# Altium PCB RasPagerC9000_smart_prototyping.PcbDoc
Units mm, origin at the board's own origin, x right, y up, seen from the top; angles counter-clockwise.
Board outline 40.39 x 44.45 mm, 2 copper layers (Top Layer, Bottom Layer); 31 components, 33 nets, 123 pads, 25 vias.
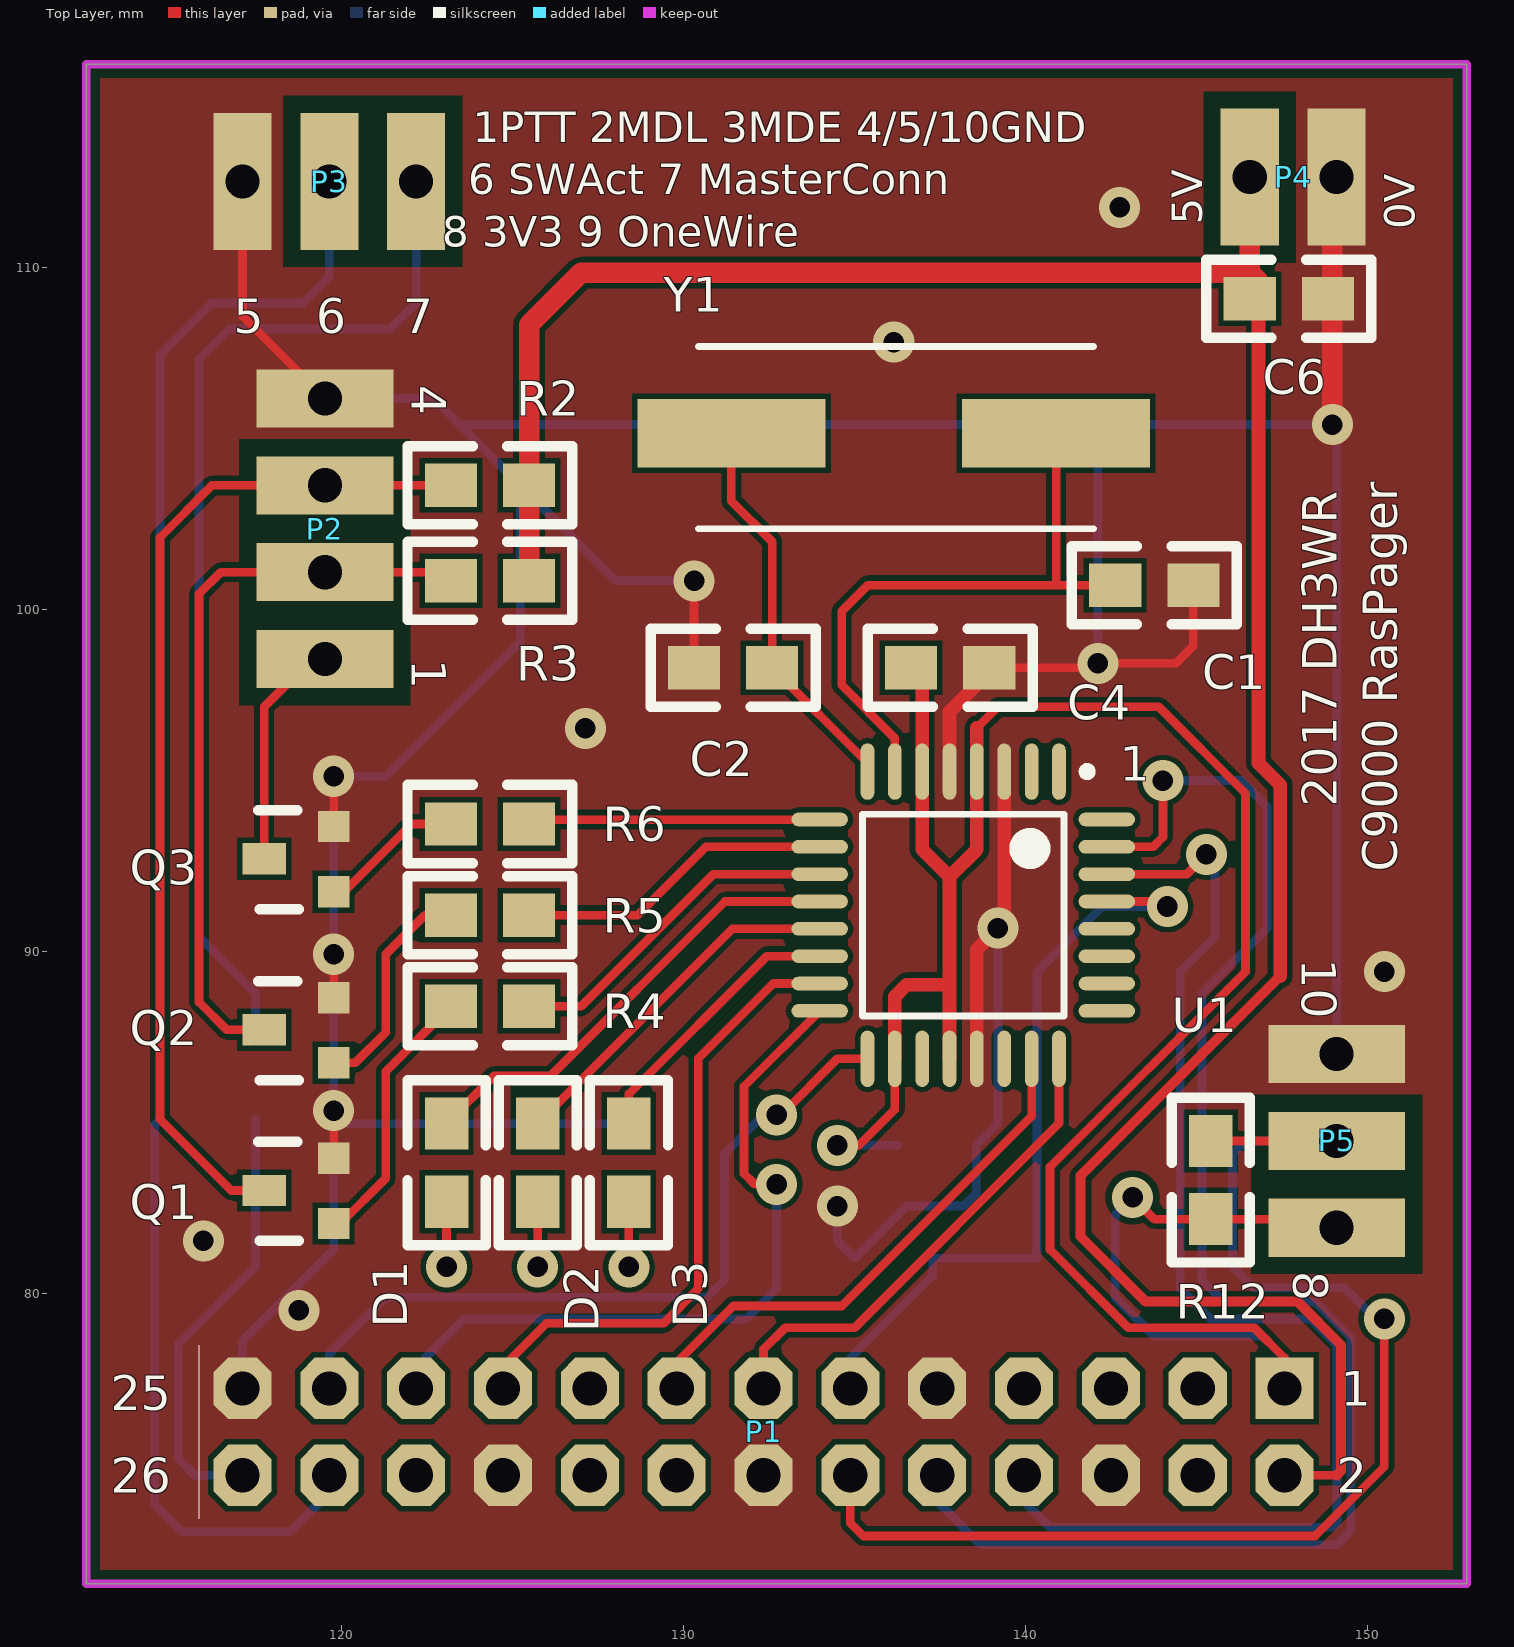
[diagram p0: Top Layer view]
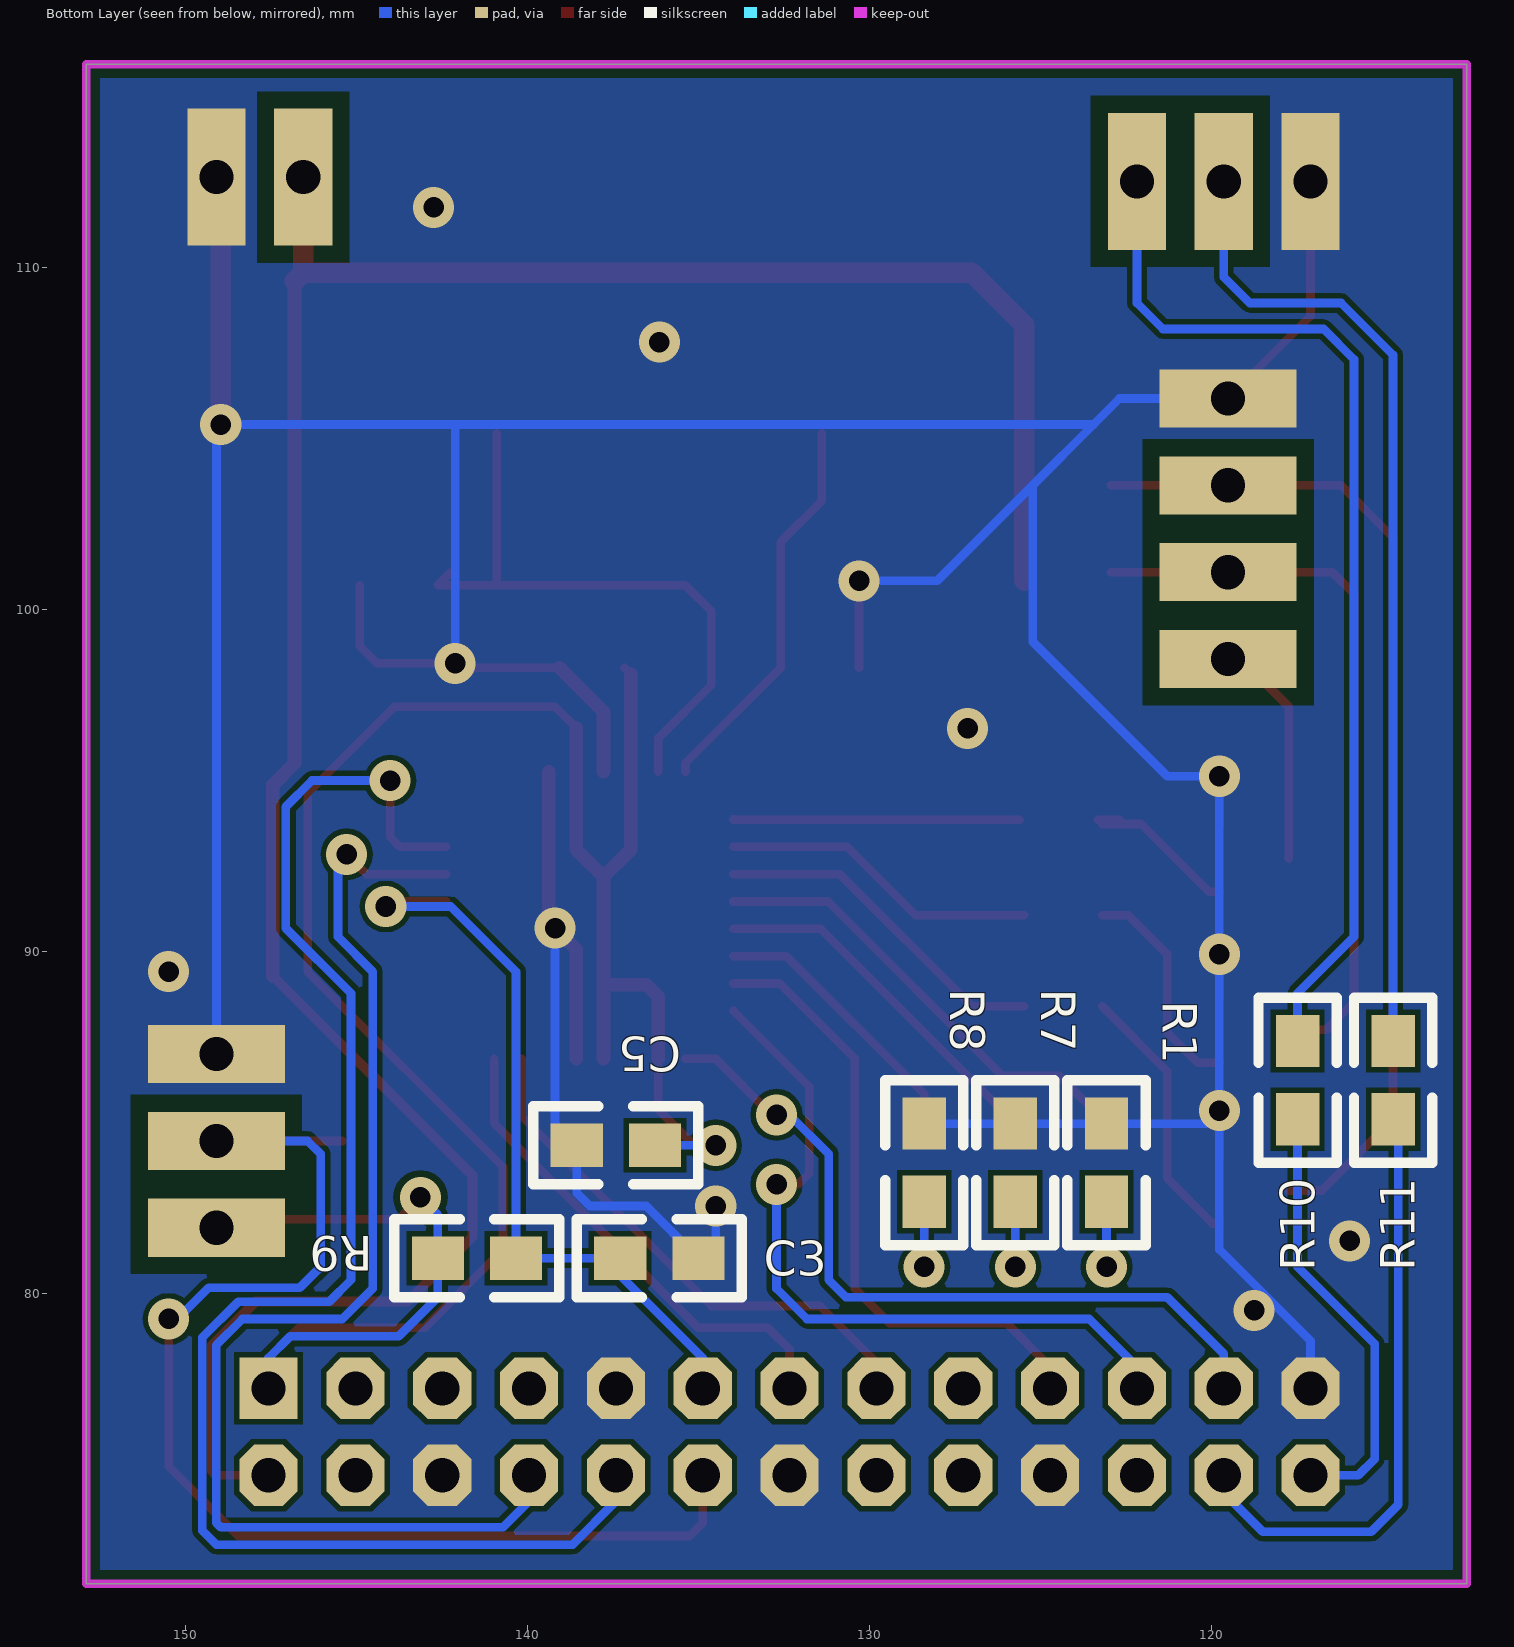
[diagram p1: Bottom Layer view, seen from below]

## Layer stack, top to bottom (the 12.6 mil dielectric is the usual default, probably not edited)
Top Solder: solder mask 0.0102, Solder Resist, Dk 3.5
Top Layer: signal copper 0.0356
Dielectric 1: dielectric 0.32, FR-4, Dk 4.8
Bottom Layer: signal copper 0.0356
Bottom Solder: solder mask 0.0102, Solder Resist, Dk 3.5

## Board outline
112.522,71.501 112.522,115.951 152.908,115.951 152.908,71.501

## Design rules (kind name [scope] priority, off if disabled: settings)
BoardOutlineClearance [All] p1: gap=0.406 except(0: Arc-SplitContinuation Track-SplitContinuation SMDPad-SplitContinuation THPad-SplitContinuation Via-SplitContinuation Fill-SplitContinuation Poly-SplitContinuation Region-SplitContinuation Text-SplitContinuation)
Clearance Clearance_Loetpad [Component Like P2 Or Component Like P3 Or Component Like P4 Or Component Like P5 vs InNet('GND')] p1: gap=0.5
Clearance [All] p2: gap=0.152 except(0.305: Arc-SMDPad Arc-THPad Track-SMDPad Track-THPad SMDPad-SMDPad SMDPad-THPad THPad-THPad)
HoleSize [All] p1: absolutevalues=TRUE maxlimit=6.223 minlimit=0.305 maxpercent=80.000 minpercent=20.000
PolygonConnect [All] p1: connectstyle=Direct reliefconductorwidth=0.254 reliefentries=4 polygonreliefangle="90 Angle" airgapwidth=0.254
RoutingVias [All] p1: holewidth=6.223 width=12.446 viastyle="Through Hole" minholewidth=0.152 minwidth=0.61 maxholewidth=0.6 maxwidth=1.2
SolderMaskExpansion [All] p1: expansion=0.102
Width [All] p1: maxlimit=2 minlimit=0.152 preferedwidth=0.254 minimp=50.000000 maximp=50.000000 favimp=50.000000
29 further rules are at their usual default settings.

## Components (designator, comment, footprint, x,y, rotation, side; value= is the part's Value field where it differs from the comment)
C1 "Cap" 0805 144.907,100.711 r180 top
C2 "Cap" 0805 130.302,98.298 r0 top
C3 "Cap" 0805 135.001,81.026 r0 bottom
C4 "Cap" 0805 138.938,98.298 r180 top
C5 "Cap" 0805 138.557,84.328 r180 bottom
C6 "Cap" 0805 148.844,109.093 r180 top
D1 "TOP LED rot" 0805 123.063,84.963 r270 top
D2 "TOP LED gelb" 0805 125.73,84.963 r270 top
D3 "TOP LED grün" 0805 128.397,84.963 r270 top
P1 "GPIO RaspberryPi" HDR2X13 147.574,77.216 r180 top
P2 "C9000_Connector" HDR1X4 119.507,98.552 r90 top
P3 "Front_LED" HDR1X3 122.174,112.522 r180 top
P4 "Power 5V" HDR1X2 146.558,112.649 r0 top
P5 "OneWire" HDR1X3 149.098,81.915 r90 top
Q1 "BC847CLT1" SOT-23 119.761,82.042 r90 top
Q2 "BC847CLT1" SOT-23 119.761,86.741 r90 top
Q3 "BC847CLT1" SOT-23 119.761,91.745 r90 top
R1 "" 0805 123.063,84.963 r270 bottom
R2 "" 0805 123.19,103.632 r0 top
R3 "" 0805 123.19,100.838 r0 top
R4 "" 0805 125.476,88.392 r180 top
R5 "" 0805 125.476,91.059 r180 top
R6 "" 0805 125.476,93.726 r180 top
R7 "" 0805 125.73,84.963 r270 bottom
R8 "" 0805 128.397,84.963 r270 bottom
R9 "" 0805 140.335,81.026 r0 bottom
R10 "" 0805 117.475,85.09 r90 bottom
R11 "" 0805 114.681,87.376 r270 bottom
R12 "" 0805 145.415,84.455 r270 top
U1 "ATmega8L-8AC" 32A_N 138.176,91.059 r270 top
Y1 "8 MHz" "HC49/4H SMX" 136.144,105.156 r90 top

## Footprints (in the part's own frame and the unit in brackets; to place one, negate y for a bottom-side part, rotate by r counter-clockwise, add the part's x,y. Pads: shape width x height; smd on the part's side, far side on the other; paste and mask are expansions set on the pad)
32A_N [mm] "Thin QFP, 32-Leads, Body 7x7mm, Pitch 0.8mm, IPC Medium Density"
  oval 1.65x0.4 smd: 1(-4.2,2.8) 2(-4.2,2) 3(-4.2,1.2) 4(-4.2,0.4) 5(-4.2,-0.4) 6(-4.2,-1.2) 7(-4.2,-2) 8(-4.2,-2.8) 17(4.2,-2.8) 18(4.2,-2) 19(4.2,-1.2) 20(4.2,-0.4) 21(4.2,0.4) 22(4.2,1.2) 23(4.2,2) 24(4.2,2.8)
  oval 0.4x1.65 smd: 9(-2.8,-4.2) 10(-2,-4.2) 11(-1.2,-4.2) 12(-0.4,-4.2) 13(0.4,-4.2) 14(1.2,-4.2) 15(2,-4.2) 16(2.8,-4.2) 25(2.8,4.2) 26(2,4.2) 27(1.2,4.2) 28(0.4,4.2) 29(-0.4,4.2) 30(-1.2,4.2) 31(-2,4.2) 32(-2.8,4.2)
  silkscreen extent -4.32,-2.95 2.95,3.75, body extent -3.5,-3.5 3.5,3.5, height 1.2
0805 [mil]
  rect 60x50 smd: 1(0,0) 2(90,0)
  silkscreen extent -50,-45 140,45
"HC49/4H SMX" [mm]
  rect 2x5.5 smd: 1(0,-4.75) 2(0,4.75)
  silkscreen extent -2.79,-5.84 2.54,5.71
HDR1X2 [mm] "Connector; Header; 2 Position"
  rect 1.7x4 hole 1: 1(0,0) 2(2.54,0)
HDR1X3 [mm] "Connector; Header; 3 Position"
  rect 1.7x4 hole 1: 1(0,0) 2(2.54,0) 3(5.08,0)
HDR1X4 [mm] "Connector; Header; 4 Position"
  rect 1.7x4 hole 1: 1(0,0) 2(2.54,0) 3(5.08,0) 4(7.62,0)
HDR2X13 [mm] "Connector; Header; 13x2 Position"
  rect 1.7x1.8 hole 1: 1(0,0)
  oct 1.7x1.8 hole 1: 2(0,2.54) 3(2.54,0) 4(2.54,2.54) 5(5.08,0) 6(5.08,2.54) 7(7.62,0) 8(7.62,2.54) 9(10.16,0) 10(10.16,2.54) 11(12.7,0) 12(12.7,2.54) 13(15.24,0) 14(15.24,2.54) 15(17.78,0) 16(17.78,2.54) 17(20.32,0) 18(20.32,2.54) 19(22.86,0) 20(22.86,2.54) 21(25.4,0) 22(25.4,2.54) 23(27.94,0) 24(27.94,2.54) 25(30.48,0) 26(30.48,2.54)
  silkscreen extent 31.75,-1.27 31.75,3.81
SOT-23 [mil]
  rect 36x36 smd: 1(0,0) 2(75,0)
  rect 36x50 smd: 3(38,80)
  silkscreen extent -20,40 94,87

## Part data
C1 C2 C3 C4 C5 C6: "Capacitor"
D1 D2 D3: library part LED_2
P1: library part "Header 13X2", "Header, 13-Pin, Dual row"
P2: library part "Header 4", "Header, 4-Pin"
P3 P5: library part "Header 3", "Header, 3-Pin"
P4: library part "Header 2", "Header, 2-Pin"
Q1 Q2 Q3: "General Purpose Transistor NPN Silicon"
R1 R2 R3 R4 R5 R6 R7 R8 R9 R10 R11 R12: library part Res2, "Resistor"
U1: "8-Bit AVR Microcontroller with 8K Bytes of In-System Programmable Flash Memory"
Y1: library part XTAL, "Crystal Oscillator"

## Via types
v1: diameter 1.2, hole 0.6, Top Layer to Bottom Layer, 25 vias

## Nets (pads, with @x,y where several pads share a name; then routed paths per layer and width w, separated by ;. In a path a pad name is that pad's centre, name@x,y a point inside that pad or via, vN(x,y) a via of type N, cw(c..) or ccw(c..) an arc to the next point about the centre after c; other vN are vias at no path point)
5V: C6.2 P1.2 P4.1 R2.2 R3.2 | length 77.3
  Top Layer w0.254: P1.2 149.098,74.676
  Top Layer w0.3: 147.447,89.281 141.605,83.439 141.605,81.661 143.51,79.756 147.955,79.756 149.225,78.486 149.225,74.803 149.098,74.676
  Top Layer w0.4: C6.2@146.812,109.601 146.812,95.504 147.447,94.869 147.447,89.281
  Top Layer w0.6: R3.2 R2.2 125.476,108.331 127,109.855 146.558,109.855 ; P4.1 146.558,109.855 ; C6.2@146.812,109.601 146.558,109.855
GND: C1.1 C2.1 C3.1 C4.1 C5.1 C6.1 P1.6 P1.9 P1.14 P1.20 P1.25 P2.4 P3.3 P4.2 P5.3 Q1.2 Q2.2 Q3.2 R1.1 R7.1 R8.1 U1.3 U1.5 U1.21 | length 160
  Top Layer w0.254: P3.3@116.561,112.522 P3.3 117.094,108.585 P2.4 ; Q1.2 v1(119.761,85.344) ; Q2.2 v1(119.761,89.916) ; Q3.2 v1(119.761,95.123) ; C2.1 v1(130.302,100.838) ; C4.1 139.065,98.298 141.986,98.298 v1(142.113,98.425) 144.399,98.425 144.907,98.933 C1.1 ; v1(139.192,90.678) v1@139.376,90.862
  Top Layer w0.4: P1.9@137.16,77.216 P1.9 ; U1.5 137.776,97.009 C4.1@139.065,98.298 ; U1.21 138.576,90.062 v1(139.192,90.678) ; v1@139.376,90.862 U1.3
  Top Layer w0.6: v1(148.971,105.41) 148.971,112.522 P4.2
  Bottom Layer w0.254: P1.25 117.094,78.613 119.761,81.28 v1(119.761,85.344) ; P2.4 122.682,106.172 123.444,105.41 ; R8.1 R7.1 R1.1 120.142,84.963 v1(119.761,85.344) ; v1(130.302,100.838) 128.016,100.838 125.222,103.632 ; v1(134.493,82.55) 134.493,81.534 C3.1 136.525,82.55 138.176,82.55 138.557,82.931 C5.1 139.192,84.963 v1(139.192,90.678) ; v1(142.113,98.425) 142.113,105.41 ; P5.3 149.098,105.283 v1(148.971,105.41) 142.113,105.41 ; v1(119.761,85.344) v1(119.761,89.916) v1(119.761,95.123) 121.285,95.123 125.222,99.06 125.222,103.632 ; 123.444,105.41 125.222,103.632 ; 123.444,105.41 142.113,105.41
  other v1: 118.745,79.502 150.495,89.408 127.127,96.52 136.144,107.823 142.748,111.76
LED_GELB: D2.1 U1.13 | length 11.7
  Top Layer w0.254: D2.1@125.603,84.455 D2.1@125.603,85.09 ; D2.1@125.73,85.217 D2.1 131.426,90.659 U1.13
  Top Layer w0.4: D2.1@125.603,85.09 D2.1@125.73,85.217
LED_GRüN: D3.1 U1.14 | length 8.1
  Top Layer w0.254: D3.1 128.397,85.828 132.428,89.859 U1.14
LED_MASTER_CONN: P1.26 R10.1 | length 12.9
  Bottom Layer w0.254: P1.26 115.697,74.676 115.22,75.153 115.22,78.517 117.475,80.772 R10.1
LED_ROT: D1.1 U1.12 | length 13.6
  Top Layer w0.254: D1.1 124.46,86.36 126.111,86.36 131.21,91.459 U1.12
LED_SW_ACTIVE: P1.24 R11.2 | length 17.8
  Bottom Layer w0.254: R11.2 114.529,84.938 114.529,73.812 115.316,73.025 118.491,73.025 119.634,74.168 P1.24
MDE_ATMEGA: R4.1 U1.11 | length 10.1
  Top Layer w0.254: R4.1 127,88.392 130.867,92.259 U1.11
MDE_C9000: P2.3 Q1.3 R2.1 | length 29.7
  Top Layer w0.254: Q1.3 116.764,83.007 114.681,85.09 114.681,102.108 116.205,103.632 P2.3 ; P2.3@120.269,103.632 R2.1@122.936,103.632
  Top Layer w0.4: P2.3 P2.3@120.142,103.632
MDL_ATMEGA: R5.1 U1.10 | length 9.3
  Top Layer w0.254: R5.1 128.651,91.059 130.651,93.059 U1.10
MDL_C9000: P2.2 Q2.3 R3.1 | length 21.6
  Top Layer w0.254: Q2.3 116.637,87.706 115.824,88.519 115.824,100.457 116.459,101.092 P2.2@119.126,101.092 ; P2.2 R3.1@122.936,101.092
  Top Layer w0.7: P2.2@119.126,101.092 P2.2
MISO: P1.21 U1.16 | length 21.9
  Top Layer w0.254: v1(132.715,83.185) 132.08,83.185 131.762,83.502 131.762,86.045 U1.16
  Bottom Layer w0.254: P1.21 122.174,77.851 123.571,79.248 131.826,79.248 132.715,80.137 v1(132.715,83.185)
MOSI: P1.19 U1.15 | length 18.5
  Top Layer w0.254: P1.19 124.714,77.851 125.984,79.121 129.413,79.121 130.429,80.137 130.429,86.868 132.62,89.059 U1.15
NetC1_2: C1.2 U1.7 Y1.1 | length 18.7
  Top Layer w0.254: U1.7 136.176,96.234 134.62,97.79 134.62,99.949 135.382,100.711 140.843,100.711 ; Y1.1 140.894,100.762 140.843,100.711 ; C1.2@142.24,101.092 C1.2 140.843,100.711
NetC2_2: C2.2 U1.8 Y1.2 | length 11.5
  Top Layer w0.254: Y1.2 131.394,103.175 132.588,101.981 C2.2 135.376,95.51 U1.8
NetD1_2: D1.2 R1.2 | length 3.8
  Top Layer w0.254: v1(123.063,80.772) D1.2
  Bottom Layer w0.254: v1(123.063,80.772) R1.2
NetD2_2: D2.2 R7.2 | length 3.8
  Top Layer w0.254: v1(125.73,80.772) D2.2
  Bottom Layer w0.254: v1(125.73,80.772) R7.2
NetD3_2: D3.2 R8.2 | length 3.8
  Top Layer w0.254: v1(128.397,80.772) D3.2
  Bottom Layer w0.254: v1(128.397,80.772) R8.2
NetP3_1: P3.1 R10.2 | length 31.4
  Top Layer w0.254: P3.1 P3.1@122.301,112.395
  Bottom Layer w0.254: R10.2 117.475,88.773 115.824,90.424 115.824,107.315 116.713,108.204 121.412,108.204 122.174,108.966 P3.1
NetP3_2: P3.2 R11.1 | length 28.8
  Bottom Layer w0.254: R11.1 114.681,107.442 116.205,108.966 118.872,108.966 119.634,109.728 P3.2
NetQ1_1: Q1.1 R4.2 | length 7.9
  Top Layer w0.254: Q1.1 119.964,82.042 121.285,83.363 121.285,86.487 R4.2
NetQ2_1: Q2.1 R5.2 | length 6.6
  Top Layer w0.254: Q2.1 120.396,86.741 121.285,87.63 121.285,89.916 122.428,91.059 R5.2
NetQ3_1: Q3.1 R6.2 | length 4.9
  Top Layer w0.254: Q3.1 120.066,91.745 122.047,93.726 R6.2 ; R6.2@122.682,93.853 R6.2@123.317,93.853
ONEWIRE: P1.12 P5.2 R12.1 | length 37.6
  Top Layer w0.254: P1.12 134.874,73.279 135.255,72.898 148.463,72.898 150.495,74.93 v1(150.495,79.248) ; R12.1 P5.2
  Bottom Layer w0.254: P5.2 146.431,84.455 146.05,84.074 146.05,80.772 146.66,80.162 149.327,80.162 150.241,79.248 v1(150.495,79.248)
PTT_ATMEGA: R6.1 U1.9 | length 8.4
  Top Layer w0.254: R6.1@125.603,93.853 133.97,93.853 U1.9
PTT_C9000: P2.1 Q3.3 | length 6.4
  Top Layer w0.254: Q3.3 117.729,97.155 P2.1@119.126,98.552
PTT_RASPI: P1.13 U1.24 | length 14.4
  Top Layer w0.254: P1.13 132.334,78.359 132.969,78.994 135.001,78.994 140.976,84.969 U1.24
RST: C3.2 P1.11 R9.1 U1.29 | length 22.5
  Top Layer w0.254: U1.29 v1@143.872,91.459
  Bottom Layer w0.254: P1.11@135.001,77.343 P1.11 134.874,78.105 137.287,80.518 C3.2 R9.1 140.335,89.408 142.24,91.313 v1(144.145,91.313)
RX_UART: P1.8 U1.30 | length 37.2
  Top Layer w0.254: U1.30 144.71,92.259 v1(145.288,92.837)
  Top Layer w0.4: P1.8@139.827,74.676 P1.8
  Bottom Layer w0.254: P1.8 139.954,73.914 140.716,73.152 148.971,73.152 149.108,73.289 149.108,78.476 148.336,79.248 145.415,79.248 144.526,80.137 144.526,89.408 145.542,90.424 145.542,92.583 v1(145.288,92.837)
SCLK: P1.23 U1.17 | length 22.5
  Top Layer w0.254: v1@132.833,85.217 132.851,85.217 134.493,86.859 U1.17
  Bottom Layer w0.254: P1.23 119.634,78.232 121.285,79.883 130.683,79.883 131.191,80.391 131.191,84.074 132.334,85.217 v1(132.715,85.217) v1@132.833,85.217
SENDDATA: P1.15 U1.23 | length 15.8
  Top Layer w0.254: P1.15 129.794,77.978 131.445,79.629 134.62,79.629 140.176,85.185 U1.23
TX_UART: P1.10 U1.31 | length 45.7
  Top Layer w0.254: U1.31 143.732,93.059 144.018,93.345 v1(144.018,94.996)
  Bottom Layer w0.254: P1.10 137.414,73.914 138.684,72.644 149.098,72.644 149.514,73.06 149.514,78.705 148.463,79.756 145.796,79.756 145.161,80.391 145.161,88.773 147.066,90.678 147.066,94.234 146.304,94.996 v1(144.018,94.996)
VCC: C4.2 C5.2 P1.1 P5.1 R9.2 R12.2 U1.4 U1.6 U1.18 U1.20 | length 75.4
  Top Layer w0.254: v1(134.493,84.328) 135.128,84.328 136.176,85.376 U1.18 ; C4.2@136.976,98.114 C4.2@137.16,98.298 ; 138.576,96.539 139.192,97.155 143.891,97.155 146.431,94.615 146.431,89.408 140.716,83.693 140.716,81.28 143.002,78.994 146.685,78.994 147.574,78.105 P1.1 ; v1(143.129,82.804) 143.764,82.169 R12.2 148.844,82.169 P5.1
  Top Layer w0.4: U1.18 136.176,88.678 136.525,89.027 137.776,89.027 ; C4.2@136.976,98.114 U1.6 136.976,92.983 137.776,92.183 ; U1.20 137.776,89.027 ; 138.576,96.539 U1.4 138.576,92.983 137.776,92.183 ; 137.776,89.027 137.776,92.183
  Bottom Layer w0.254: v1(134.493,84.328) C5.2 ; v1(143.129,82.804) 142.621,82.296 R9.2 142.621,79.883 143.764,78.74 146.939,78.74 147.574,78.105 P1.1
pads on no net: P1.3 P1.4 P1.5 P1.7 P1.16 P1.17 P1.18 P1.22 U1.1 U1.2 U1.19 U1.22 U1.25 U1.26 U1.27 U1.28 U1.32
copper on no net:
  other v1: 115.951,81.534

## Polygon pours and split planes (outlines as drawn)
GND on Top Layer "Bottom Layer-GND" (solid, remove dead copper, pour order 8): 112.522,115.951 152.908,115.951 152.908,71.501 112.522,71.501
GND on Bottom Layer "Bottom Layer-GND" (solid, remove dead copper, pour order 10): 112.522,115.951 152.908,115.951 152.908,71.501 112.522,71.501

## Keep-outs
Keep-Out Layer:
  the board outline again, w0.254

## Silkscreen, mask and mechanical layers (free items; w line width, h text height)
Top Overlay:
  text "1PTT 2MDL 3MDE 4/5/10GND" at 123.825,113.665 h0.9
  text "6 SWAct 7 MasterConn" at 123.698,112.141 h0.9
  text "5V" at 145.161,111.252 h0.9 r90
  text "0V" at 151.384,111.125 h0.9 r90
  text "8 3V3 9 OneWire" at 122.936,110.617 h0.9
  text "5" at 116.84,108.077 h1
  text "6" at 119.253,108.077 h1
  text "7" at 121.793,108.077 h1
  text "4" at 122.047,106.553 h1 r270
  text "1" at 122.047,98.552 h1 r270
  text "1" at 142.748,94.996 h1
  text "2017 DH3WR" at 149.098,94.234 h1 r90
  text "C9000 RasPager" at 150.876,92.329 h1 r90
  text "10" at 148.082,89.789 h1 r270
  text "8" at 147.828,80.645 h1 r270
